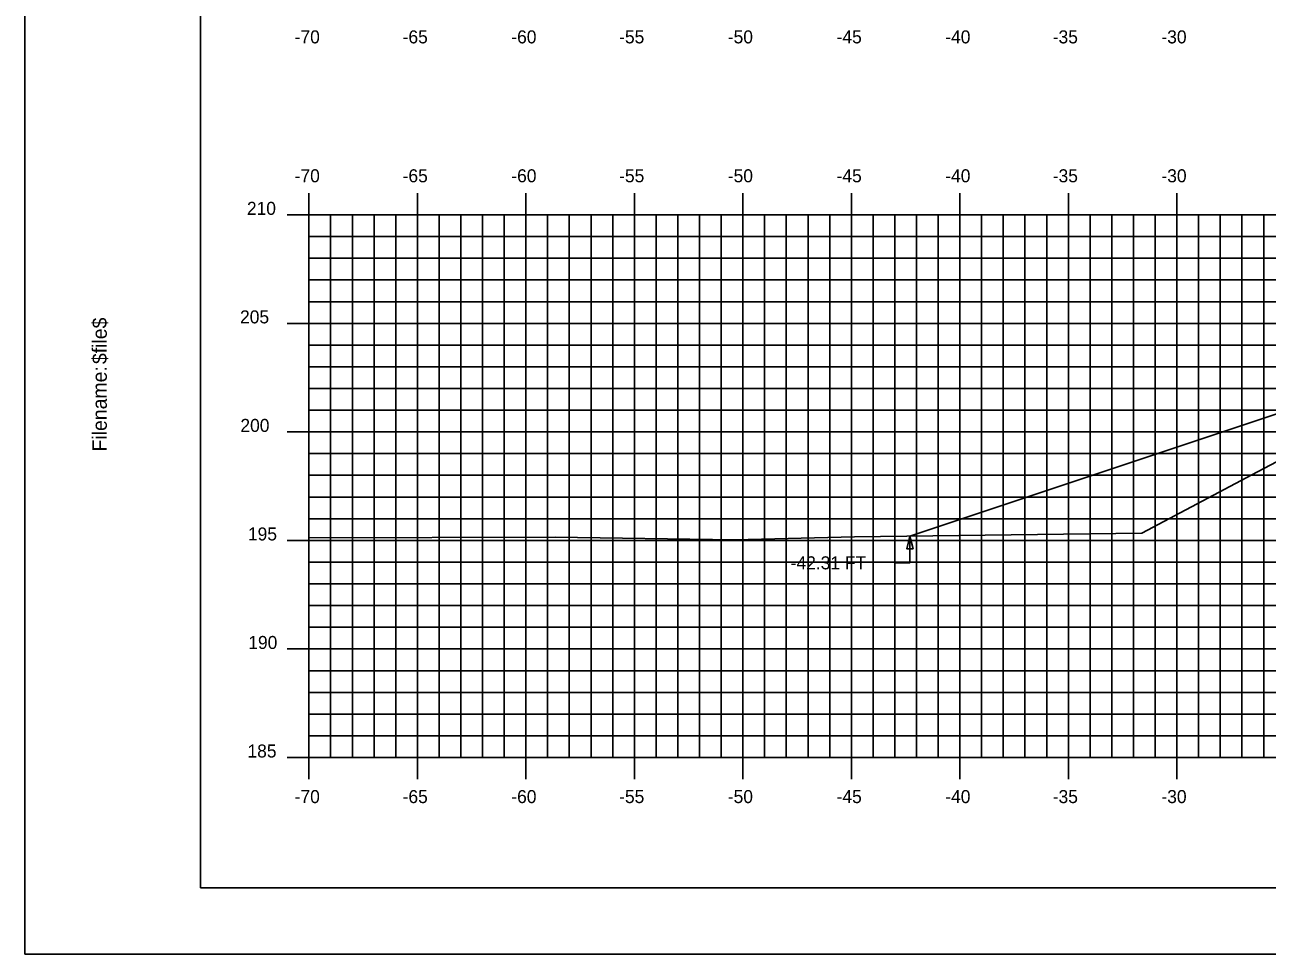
# Model space of a CAD drawing. Extents: x 1138763 to 1138933, y 608981 to 609091.
# Drawn here: x 1138763.1 to 1138820.4, y 608981.3 to 609024.1 of the extents above; entities that cross this region are included whole.
import ezdxf

# ---------------------------------------------------------------- set-up
doc = ezdxf.new("R2010")
doc.units = 0
for name, color, linetype in [('BORDER', 7, 'Continuous'), ('D_Roadway_SlopeLines', 7, 'Continuous'), ('D_Text_Standard', 7, 'Continuous'), ('H_V ANNOTATION', 7, 'Continuous'), ('MAJOR', 7, 'Continuous'), ('MINOR', 7, 'Continuous'), ('PLOT BOUNDARY', 7, 'Continuous'), ('S_Roadway_Centerline', 7, 'Continuous')]:
    doc.layers.add(name, color=color, linetype=linetype)

msp = doc.modelspace()

# ---------------------------------------------------------------- linework, layer by layer
msp.add_lwpolyline([(1138803.882, 609000.533), (1138817.659, 609005.125), (1138820.659, 609006.125), (1138828.191, 609008.636), (1138828.192, 609008.636), (1138835.192, 609008.916), (1138846.192, 609009.136), (1138857.192, 609008.916), (1138864.192, 609008.636), (1138871.724, 609006.125), (1138874.724, 609005.125), (1138889.689, 609000.137)])
at = {"layer": 'BORDER'}
msp.add_lwpolyline([(1138771.192, 608984.335), (1138931.192, 608984.335), (1138931.192, 609089.335), (1138771.192, 609089.335)], close=True, dxfattribs=at)
at = {"layer": 'D_Roadway_SlopeLines'}
for points in [[(1138820.659, 609006.125), (1138817.659, 609005.125)], [(1138817.659, 609005.125), (1138803.882, 609000.533)]]:
    msp.add_lwpolyline(points, dxfattribs=at)
at = {"layer": 'D_Text_Standard'}
msp.add_lwpolyline([(1138803.882, 609000.533), (1138803.889, 608999.304), (1138803.209, 608999.304)], dxfattribs=at)
msp.add_lwpolyline([(1138803.882, 609000.533), (1138804.031, 608999.952), (1138803.74, 608999.95)], close=True, dxfattribs=at)
at = {"layer": 'MAJOR'}
for p, q in [((1138776.192, 609016.337), (1138776.192, 609015.335)), ((1138781.192, 609016.337), (1138781.192, 609015.335)), ((1138786.192, 609016.337), (1138786.192, 609015.335)), ((1138791.192, 609016.337), (1138791.192, 609015.335)), ((1138796.192, 609016.337), (1138796.192, 609015.335)), ((1138801.192, 609016.337), (1138801.192, 609015.335)), ((1138806.192, 609016.337), (1138806.192, 609015.335)), ((1138811.192, 609016.337), (1138811.192, 609015.335)), ((1138816.192, 609016.337), (1138816.192, 609015.335)), ((1138775.19, 609015.335), (1138776.192, 609015.335)), ((1138776.192, 609015.335), (1138916.192, 609015.335)), ((1138776.192, 608990.335), (1138776.192, 609015.335)), ((1138776.192, 608990.335), (1138776.192, 609015.335)), ((1138776.192, 609015.335), (1138916.192, 609015.335)), ((1138781.192, 608990.335), (1138781.192, 609015.335)), ((1138786.192, 608990.335), (1138786.192, 609015.335)), ((1138791.192, 608990.335), (1138791.192, 609015.335)), ((1138796.192, 608990.335), (1138796.192, 609015.335)), ((1138801.192, 608990.335), (1138801.192, 609015.335)), ((1138806.192, 608990.335), (1138806.192, 609015.335)), ((1138811.192, 608990.335), (1138811.192, 609015.335)), ((1138816.192, 608990.335), (1138816.192, 609015.335)), ((1138775.19, 609010.335), (1138776.192, 609010.335)), ((1138776.192, 609010.335), (1138916.192, 609010.335)), ((1138775.19, 609005.335), (1138776.192, 609005.335)), ((1138776.192, 609005.335), (1138916.192, 609005.335)), ((1138775.19, 609000.335), (1138776.192, 609000.335)), ((1138776.192, 609000.335), (1138916.192, 609000.335)), ((1138775.19, 608995.335), (1138776.192, 608995.335)), ((1138776.192, 608995.335), (1138916.192, 608995.335)), ((1138775.19, 608990.335), (1138776.192, 608990.335)), ((1138776.192, 608990.335), (1138916.192, 608990.335)), ((1138776.192, 608990.335), (1138916.192, 608990.335)), ((1138776.192, 608989.333), (1138776.192, 608990.335)), ((1138781.192, 608989.333), (1138781.192, 608990.335)), ((1138786.192, 608989.333), (1138786.192, 608990.335)), ((1138791.192, 608989.333), (1138791.192, 608990.335)), ((1138796.192, 608989.333), (1138796.192, 608990.335)), ((1138801.192, 608989.333), (1138801.192, 608990.335)), ((1138806.192, 608989.333), (1138806.192, 608990.335)), ((1138811.192, 608989.333), (1138811.192, 608990.335)), ((1138816.192, 608989.333), (1138816.192, 608990.335))]:
    msp.add_line(p, q, dxfattribs=at)
at = {"layer": 'MINOR'}
for p, q in [((1138777.192, 608990.335), (1138777.192, 609015.335)), ((1138778.192, 608990.335), (1138778.192, 609015.335)), ((1138779.192, 608990.335), (1138779.192, 609015.335)), ((1138780.192, 608990.335), (1138780.192, 609015.335)), ((1138782.192, 608990.335), (1138782.192, 609015.335)), ((1138783.192, 608990.335), (1138783.192, 609015.335)), ((1138784.192, 608990.335), (1138784.192, 609015.335)), ((1138785.192, 608990.335), (1138785.192, 609015.335)), ((1138787.192, 608990.335), (1138787.192, 609015.335)), ((1138788.192, 608990.335), (1138788.192, 609015.335)), ((1138789.192, 608990.335), (1138789.192, 609015.335)), ((1138790.192, 608990.335), (1138790.192, 609015.335)), ((1138792.192, 608990.335), (1138792.192, 609015.335)), ((1138793.192, 608990.335), (1138793.192, 609015.335)), ((1138794.192, 608990.335), (1138794.192, 609015.335)), ((1138795.192, 608990.335), (1138795.192, 609015.335)), ((1138797.192, 608990.335), (1138797.192, 609015.335)), ((1138798.192, 608990.335), (1138798.192, 609015.335)), ((1138799.192, 608990.335), (1138799.192, 609015.335)), ((1138800.192, 608990.335), (1138800.192, 609015.335)), ((1138802.192, 608990.335), (1138802.192, 609015.335)), ((1138803.192, 608990.335), (1138803.192, 609015.335)), ((1138804.192, 608990.335), (1138804.192, 609015.335)), ((1138805.192, 608990.335), (1138805.192, 609015.335)), ((1138807.192, 608990.335), (1138807.192, 609015.335)), ((1138808.192, 608990.335), (1138808.192, 609015.335)), ((1138809.192, 608990.335), (1138809.192, 609015.335)), ((1138810.192, 608990.335), (1138810.192, 609015.335)), ((1138812.192, 608990.335), (1138812.192, 609015.335)), ((1138813.192, 608990.335), (1138813.192, 609015.335)), ((1138814.192, 608990.335), (1138814.192, 609015.335)), ((1138815.192, 608990.335), (1138815.192, 609015.335)), ((1138817.192, 608990.335), (1138817.192, 609015.335)), ((1138818.192, 608990.335), (1138818.192, 609015.335)), ((1138819.192, 608990.335), (1138819.192, 609015.335)), ((1138820.192, 608990.335), (1138820.192, 609015.335)), ((1138776.192, 609014.335), (1138916.192, 609014.335)), ((1138776.192, 609014.335), (1138777.194, 609014.335)), ((1138776.192, 609013.335), (1138916.192, 609013.335)), ((1138776.192, 609013.335), (1138777.194, 609013.335)), ((1138776.192, 609012.335), (1138916.192, 609012.335)), ((1138776.192, 609012.335), (1138777.194, 609012.335)), ((1138776.192, 609011.335), (1138916.192, 609011.335)), ((1138776.192, 609011.335), (1138777.194, 609011.335)), ((1138776.192, 609009.335), (1138916.192, 609009.335)), ((1138776.192, 609009.335), (1138777.194, 609009.335)), ((1138776.192, 609008.335), (1138916.192, 609008.335)), ((1138776.192, 609008.335), (1138777.194, 609008.335)), ((1138776.192, 609007.335), (1138916.192, 609007.335)), ((1138776.192, 609007.335), (1138777.194, 609007.335)), ((1138776.192, 609006.335), (1138916.192, 609006.335)), ((1138776.192, 609006.335), (1138777.194, 609006.335)), ((1138776.192, 609004.335), (1138916.192, 609004.335)), ((1138776.192, 609004.335), (1138777.194, 609004.335)), ((1138776.192, 609003.335), (1138916.192, 609003.335)), ((1138776.192, 609003.335), (1138777.194, 609003.335)), ((1138776.192, 609002.335), (1138916.192, 609002.335)), ((1138776.192, 609002.335), (1138777.194, 609002.335)), ((1138776.192, 609001.335), (1138916.192, 609001.335)), ((1138776.192, 609001.335), (1138777.194, 609001.335)), ((1138776.192, 608999.335), (1138916.192, 608999.335)), ((1138776.192, 608999.335), (1138777.194, 608999.335)), ((1138776.192, 608998.335), (1138916.192, 608998.335)), ((1138776.192, 608998.335), (1138777.194, 608998.335)), ((1138776.192, 608997.335), (1138916.192, 608997.335)), ((1138776.192, 608997.335), (1138777.194, 608997.335)), ((1138776.192, 608996.335), (1138916.192, 608996.335)), ((1138776.192, 608996.335), (1138777.194, 608996.335)), ((1138776.192, 608994.335), (1138916.192, 608994.335)), ((1138776.192, 608994.335), (1138777.194, 608994.335)), ((1138776.192, 608993.335), (1138916.192, 608993.335)), ((1138776.192, 608993.335), (1138777.194, 608993.335)), ((1138776.192, 608992.335), (1138916.192, 608992.335)), ((1138776.192, 608992.335), (1138777.194, 608992.335)), ((1138776.192, 608991.335), (1138916.192, 608991.335)), ((1138776.192, 608991.335), (1138777.194, 608991.335))]:
    msp.add_line(p, q, dxfattribs=at)
at = {"layer": 'PLOT BOUNDARY'}
msp.add_lwpolyline([(1138763.099, 608981.276), (1138933.099, 608981.276), (1138933.099, 609091.276), (1138763.099, 609091.276)], close=True, dxfattribs=at)
at = {"layer": 'S_Roadway_Centerline'}
msp.add_lwpolyline([(1138776.192, 609000.463), (1138787.534, 609000.483), (1138795.813, 609000.369), (1138801.34, 609000.501), (1138814.583, 609000.668), (1138819.911, 609003.49), (1138824.614, 609005.971), (1138825.62, 609006.374), (1138831.811, 609008.515), (1138835.077, 609008.967), (1138835.825, 609009.136), (1138845.105, 609009.195), (1138846.445, 609009.215), (1138847.926, 609009.183), (1138857.376, 609008.967), (1138857.81, 609008.955), (1138860.36, 609008.824), (1138864.437, 609006.865), (1138878.846, 609000.433), (1138878.887, 609000.44), (1138911.071, 608999.536), (1138914.413, 608999.513), (1138916.192, 608999.492)], dxfattribs=at)

# ---------------------------------------------------------------- texts
at = {"layer": 'BORDER'}
for s, p in [('$file$', (1138766.877, 609008.461)), ('Filename:', (1138766.877, 609004.433))]:
    msp.add_text(s, height=0.6696, rotation=90, dxfattribs=at).set_placement(p)
at = {"layer": 'D_Text_Standard'}
msp.add_text('-42.31 FT', height=0.6, dxfattribs=at).set_placement((1138798.394, 608999.004))
at = {"layer": 'H_V ANNOTATION'}
for s, p in [('-70', (1138775.534, 609023.235)), ('-65', (1138780.51, 609023.235)), ('-60', (1138785.518, 609023.235)), ('-55', (1138790.488, 609023.235)), ('-50', (1138795.496, 609023.235)), ('-45', (1138800.51, 609023.235)), ('-40', (1138805.518, 609023.235)), ('-35', (1138810.472, 609023.235)), ('-30', (1138815.48, 609023.235)), ('-70', (1138775.534, 609016.835)), ('-65', (1138780.51, 609016.835)), ('-60', (1138785.518, 609016.835)), ('-55', (1138790.488, 609016.835)), ('-50', (1138795.496, 609016.835)), ('-45', (1138800.51, 609016.835)), ('-40', (1138805.518, 609016.835)), ('-35', (1138810.472, 609016.835)), ('-30', (1138815.48, 609016.835)), ('210', (1138773.333, 609015.335)), ('205', (1138773.017, 609010.335)), ('200', (1138773.033, 609005.335)), ('195', (1138773.381, 609000.335)), ('190', (1138773.397, 608995.335)), ('185', (1138773.359, 608990.335)), ('-70', (1138775.534, 608988.235)), ('-65', (1138780.51, 608988.235)), ('-60', (1138785.518, 608988.235)), ('-55', (1138790.488, 608988.235)), ('-50', (1138795.496, 608988.235)), ('-45', (1138800.51, 608988.235)), ('-40', (1138805.518, 608988.235)), ('-35', (1138810.472, 608988.235)), ('-30', (1138815.48, 608988.235))]:
    msp.add_text(s, height=0.6, dxfattribs=at).set_placement(p)
at = {"layer": 'MAJOR'}
msp.add_text('-', height=0.006, dxfattribs=at).set_placement((1138776.188, 608990.335))

doc.saveas('drawing.dxf')
